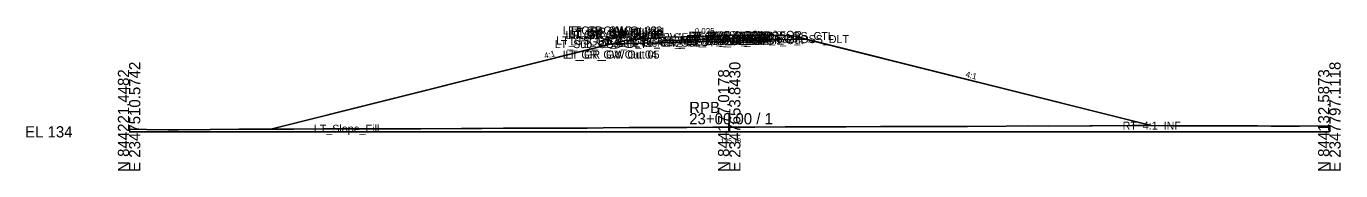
# Model space of a CAD drawing. Extents: x -76 to 2347760, y -10 to 844216.
# Drawn here: x -75.7 to 252.8, y 7990.3 to 8026.3 of the extents above; entities that cross this region are included whole.
import ezdxf

# ---------------------------------------------------------------- set-up
doc = ezdxf.new("R2010")
doc.units = 0
for name, color, linetype in [('Default', 7, 'Continuous'), ('Exist Cross Section Cell', 7, 'Continuous'), ('Exist XS Center Line Elevation Label', 7, 'Continuous'), ('Exist XS Ground Line', 7, 'Continuous'), ('Prop CMT Pvmt Course 1', 7, 'Continuous'), ('Prop CMT Pvmt Course 2', 7, 'Continuous'), ('Prop CMT Pvmt Course 3', 7, 'Continuous'), ('Prop CMT Pvmt Surface', 7, 'Continuous'), ('Prop CMT Pvmt Surface Shoulder', 7, 'Continuous'), ('Prop CMT Shld Paved Course 1', 7, 'Continuous'), ('Prop CMT Shld Paved Course 2', 7, 'Continuous'), ('Prop CMT Shld Paved Course 3', 7, 'Continuous'), ('Prop CMT Slope Grass', 7, 'Continuous'), ('Prop CMT Subgrade Earthwork', 7, 'Continuous'), ('Prop XS Earthwork Shape', 7, 'Continuous'), ('Prop XS Side Slope Text', 7, 'Continuous'), ('Scratch_Level_0', 7, 'Continuous')]:
    doc.layers.add(name, color=color, linetype=linetype)

msp = doc.modelspace()

# ---------------------------------------------------------------- linework, layer by layer
at = {"layer": 'Exist Cross Section Cell'}
for p, q in [((100, 8000), (100, 8004.67)), ((-50, 8000), (-16.56, 8000)), ((-50, 8000), (100, 8000)), ((-16.56, 8000), (-16.53, 8000)), ((100, 8000), (250, 8000))]:
    msp.add_line(p, q, dxfattribs=at)
at = {"layer": 'Exist XS Ground Line'}
for points in [[(-50, 8000.62), (-45.62, 8000.58), (-40.19, 8000.51), (-37.75, 8000.52), (-29.72, 8000.58), (-22.58, 8000.63), (-19.25, 8000.64), (-16.56, 8000.64)], [(-16.56, 8000.64), (-16.53, 8000.64)], [(-16.53, 8000.64), (-11.86, 8000.64), (-9.51, 8000.64), (-8.78, 8000.64), (-1.52, 8000.72), (1.69, 8000.75), (7.78, 8000.78), (12.16, 8000.78), (21.9, 8000.78), (22.63, 8000.78), (22.95, 8000.78), (33.1, 8000.79), (38.13, 8000.81), (43.57, 8000.88), (53.31, 8000.94), (54.04, 8000.94), (55.67, 8000.94), (64.51, 8000.95), (68.48, 8000.97), (74.98, 8001.05), (81.49, 8001.04)], [(81.49, 8001.04), (83.66, 8001.04), (85.45, 8001.05), (89.43, 8001.09), (95.92, 8001.17), (98.84, 8001.18), (100, 8001.18), (106.39, 8001.2), (114.01, 8001.25), (116.86, 8001.24), (123.19, 8001.23), (127.33, 8001.22), (129.19, 8001.24), (137.8, 8001.34), (144.37, 8001.32), (148.27, 8001.3), (156.95, 8001.35), (158.74, 8001.35), (159.54, 8001.36), (169.21, 8001.43), (174.72, 8001.45), (179.68, 8001.44), (190.15, 8001.53), (190.71, 8001.53), (200.62, 8001.56), (205.08, 8001.55), (211.09, 8001.53), (220.25, 8001.46), (221.56, 8001.46), (224.47, 8001.45), (232.03, 8001.46), (235.43, 8001.41), (242.5, 8001.41), (250, 8001.48)]]:
    msp.add_lwpolyline(points, dxfattribs=at)
at = {"layer": 'Prop CMT Pvmt Course 1'}
for p, q in [((100, 8023.99), (88, 8023.69)), ((88, 8023.69), (88, 8022.85)), ((88, 8022.85), (100, 8023.15)), ((100, 8023.99), (104, 8024.09)), ((100, 8023.15), (100, 8023.99)), ((100, 8023.99), (100, 8023.99)), ((100, 8023.99), (100, 8023.15)), ((100, 8023.15), (100, 8023.99)), ((100, 8023.15), (100, 8023.99)), ((100, 8023.99), (100, 8023.99)), ((100, 8023.99), (100, 8023.15)), ((100, 8023.15), (100, 8023.99)), ((104, 8023.25), (100, 8023.15)), ((100, 8023.15), (100, 8023.15)), ((100, 8023.15), (100, 8023.15)), ((104, 8024.09), (104, 8023.25))]:
    msp.add_line(p, q, dxfattribs=at)
at = {"layer": 'Prop CMT Pvmt Course 2'}
for p, q in [((88, 8022.85), (100, 8023.15)), ((100, 8023.15), (88, 8022.85)), ((88, 8022.85), (88, 8022.85)), ((104, 8023.25), (100, 8023.15)), ((100, 8023.15), (104, 8023.25)), ((100, 8023.15), (100, 8023.15)), ((100, 8023.15), (100, 8023.15)), ((104, 8023.25), (104, 8023.25))]:
    msp.add_line(p, q, dxfattribs=at)
at = {"layer": 'Prop CMT Pvmt Course 3'}
for p, q in [((100, 8023.15), (88, 8022.85)), ((88, 8022.85), (88, 8022.35)), ((100, 8023.15), (104, 8023.25)), ((100, 8022.65), (100, 8023.15)), ((100, 8022.65), (100, 8023.15)), ((104, 8023.25), (104, 8022.75)), ((88, 8022.35), (100, 8022.65)), ((104, 8022.75), (100, 8022.65))]:
    msp.add_line(p, q, dxfattribs=at)
at = {"layer": 'Prop CMT Pvmt Surface'}
for q in [(88, 8023.69), (104, 8024.09)]:
    msp.add_line((100, 8023.99), q, dxfattribs=at)
at = {"layer": 'Prop CMT Pvmt Surface Shoulder'}
for p, q in [((88, 8023.69), (84, 8023.59)), ((104, 8024.09), (108, 8024.19))]:
    msp.add_line(p, q, dxfattribs=at)
at = {"layer": 'Prop CMT Shld Paved Course 1'}
for p, q in [((88, 8023.69), (84, 8023.59)), ((84, 8023.59), (84, 8022.75)), ((84, 8022.75), (88, 8022.85)), ((88, 8022.85), (88, 8023.69)), ((104, 8024.09), (108, 8024.19)), ((104, 8023.25), (104, 8024.09)), ((108, 8023.35), (104, 8023.25)), ((108, 8024.19), (108, 8023.35))]:
    msp.add_line(p, q, dxfattribs=at)
at = {"layer": 'Prop CMT Shld Paved Course 2'}
for p, q in [((88, 8022.85), (84, 8022.75)), ((84, 8022.75), (88, 8022.85)), ((88, 8022.85), (88, 8022.85)), ((104, 8023.25), (108, 8023.35)), ((108, 8023.35), (104, 8023.25)), ((104, 8023.25), (104, 8023.25)), ((108, 8023.35), (108, 8023.35)), ((84, 8022.75), (84, 8022.75))]:
    msp.add_line(p, q, dxfattribs=at)
at = {"layer": 'Prop CMT Shld Paved Course 3'}
for p, q in [((88, 8022.85), (84, 8022.75)), ((88, 8022.35), (88, 8022.85)), ((104, 8023.25), (108, 8023.35)), ((104, 8022.75), (104, 8023.25)), ((108.99, 8022.88), (104, 8022.75)), ((108, 8023.35), (108.5, 8023.36)), ((108.5, 8023.36), (108.99, 8022.88)), ((83.5, 8022.74), (82.99, 8022.23)), ((82.99, 8022.23), (88, 8022.35)), ((84, 8022.75), (83.5, 8022.74))]:
    msp.add_line(p, q, dxfattribs=at)
at = {"layer": 'Prop CMT Slope Grass'}
for p, q in [((73.99, 8022.78), (-14.58, 8000.64)), ((84, 8023.59), (73.99, 8022.78)), ((108, 8024.19), (116, 8023.91)), ((116, 8023.91), (205.45, 8001.54))]:
    msp.add_line(p, q, dxfattribs=at)
at = {"layer": 'Prop CMT Subgrade Earthwork'}
for p, q in [((104, 8022.75), (108.99, 8022.88)), ((108.99, 8022.88), (119.1, 8023.13)), ((82.99, 8022.23), (70.51, 8021.91)), ((88, 8022.35), (82.99, 8022.23)), ((100, 8022.65), (88, 8022.35)), ((100, 8022.65), (104, 8022.75))]:
    msp.add_line(p, q, dxfattribs=at)
at = {"layer": 'Prop XS Earthwork Shape'}
msp.add_lwpolyline([(190.71, 8001.53), (200.62, 8001.56), (205.08, 8001.55), (205.45, 8001.54), (119.1, 8023.13), (108.99, 8022.88), (104, 8022.75), (100, 8022.65), (88, 8022.35), (82.99, 8022.23), (70.51, 8021.91), (-14.58, 8000.64), (-11.86, 8000.64), (-9.51, 8000.64), (-8.78, 8000.64), (-1.52, 8000.72), (1.69, 8000.75), (7.78, 8000.78), (12.16, 8000.78), (21.9, 8000.78), (22.63, 8000.78), (22.95, 8000.78), (33.1, 8000.79), (38.13, 8000.81), (43.57, 8000.88), (53.31, 8000.94), (54.04, 8000.94), (55.67, 8000.94), (64.51, 8000.95), (68.48, 8000.97), (74.98, 8001.05), (81.49, 8001.04), (83.66, 8001.04), (85.45, 8001.05), (89.43, 8001.09), (95.92, 8001.17), (98.84, 8001.18), (100, 8001.18), (106.39, 8001.2), (114.01, 8001.25), (116.86, 8001.24), (123.19, 8001.23), (127.33, 8001.22), (129.19, 8001.24), (137.8, 8001.34), (144.37, 8001.32), (148.27, 8001.3), (156.95, 8001.35), (158.74, 8001.35), (159.54, 8001.36), (169.21, 8001.43), (174.72, 8001.45), (179.68, 8001.44), (190.15, 8001.53)], close=True, dxfattribs=at)

# ---------------------------------------------------------------- texts
at = {"layer": 'Default'}
msp.add_text('-', height=0.0001, dxfattribs=at).set_placement((-50, 8000))
at = {"layer": 'Exist Cross Section Cell'}
for s, p in [('E 2347510.5742', (-47.2, 7990)), ('E 2347510.5742', (-47.2, 7990)), ('E 2347653.8430', (102.8, 7990)), ('E 2347797.1118', (252.8, 7990)), ('E 2347797.1118', (252.8, 7990)), ('N 844221.4482', (-50, 7990)), ('N 844221.4482', (-50, 7990)), ('N 844177.0178', (100, 7990)), ('N 844132.5873', (250, 7990)), ('N 844132.5873', (250, 7990))]:
    msp.add_text(s, height=2.8, rotation=90, dxfattribs=at).set_placement(p)
for s, p in [('RPB', (90, 8004.67)), ('23+00.00 / 1', (90, 8001.87)), ('EL 134', (-76, 7998.6)), ('EL 134', (-76, 7998.6))]:
    msp.add_text(s, height=2.8, dxfattribs=at).set_placement(p)
at = {"layer": 'Exist XS Center Line Elevation Label'}
msp.add_text('135.18', height=1.2, dxfattribs=at).set_placement((97.89, 7997.17))
at = {"layer": 'Prop XS Side Slope Text'}
for s, rotation, p in [('0.025', 1.4321, (91.38, 8024.32)), ('4:1', 14.0362, (53.91, 8018.19)), ('4:1', 345.9638, (158.96, 8013.69))]:
    msp.add_text(s, height=1.5, rotation=rotation, dxfattribs=at).set_placement(p)
at = {"layer": 'Scratch_Level_0'}
for s, p in [('LT_GR_GW Out 03', (58.43, 8024.28)), ('LT_GR_GW Out 02', (59.77, 8024.28)), ('LT_Sub_OSS_DLT', (56.39, 8020.88)), ('LT_GS_OS_GR_Face_GW', (56.75, 8021.78)), ('LT_GR_GW Out 06', (59.05, 8023.12)), ('LT_GR_GW Out 09', (59.77, 8023.7)), ('LT_GR_GW Out 07', (59.77, 8023.12)), ('LT_GR_GW Out 08', (60.04, 8023.41)), ('LT_GS_OS_CTL', (60.36, 8021.54)), ('LT_GR_GW Out 01', (60.6, 8023.99)), ('LT_Sub_Trench_Out', (67.19, 8021.23)), ('LT_PS3_Shelf_Out', (69.48, 8021.74)), ('LT_PS3_OEOP', (74.24, 8021.75)), ('LT_PS2_OEOP', (74.24, 8021.75)), ('LT_PS1_OEOP', (74.8, 8022.59)), ('LT_Sub_OEOT', (78.08, 8021.35)), ('LT_PV3_OEOT', (78.17, 8021.85)), ('LT_PV2_OEOT', (78.17, 8021.85)), ('LT_PV1_OEOT', (78.74, 8022.69)), ('RT_Sub_OEEOP', (89.17, 8021.65)), ('LT_Sub_OEEOP', (89.21, 8021.65)), ('RT_PV2_OEEOP', (89.26, 8022.15)), ('RT_PV3_OEEOP', (89.26, 8022.15)), ('LT_PV2_OEEOP', (89.31, 8022.15)), ('LT_PV3_OEEOP', (89.31, 8022.15)), ('RT_PV1_OEEOP', (89.83, 8022.99)), ('LT_PV1_OEEOP', (89.87, 8022.99)), ('RT_PV2_IEEOP', (89.91, 8022.15)), ('LT_PV2_IEEOP', (89.95, 8022.15)), ('RT_PV1_IEEOP', (90.47, 8022.99)), ('LT_PV1_IEEOP', (90.52, 8022.99)), ('RT_Sub_Trench_Out', (93.15, 8021.88)), ('PV2_PGL', (93.91, 8022.15)), ('RT_Sub_OEOT', (94.03, 8021.75)), ('RT_PV3_OEOT', (94.13, 8022.25)), ('RT_PV2_OEOT', (94.13, 8022.25)), ('RT_PS3_Shelf_Out', (94.44, 8022.36)), ('PV1_PGL', (94.47, 8022.99)), ('RT_PV1_OEOT', (94.69, 8023.09)), ('RT_PS3_OEOP', (98.19, 8022.35)), ('RT_PS2_OEOP', (98.19, 8022.35)), ('RT_PS1_OEOP', (98.76, 8023.19)), ('RT_GS_OS_CTL', (105.32, 8022.91)), ('RT_Sub_OSS_DLT', (106.46, 8022.13)), ('LT_GR_GW Out 04', (58.43, 8018.28)), ('LT_GR_GW Out 05', (59.1, 8018.28)), ('LT_Slope_Fill', (-3.82, 7999.77)), ('RT_4:1_INF', (198.33, 8000.54))]:
    msp.add_text(s, height=2, dxfattribs=at).set_placement(p)

doc.saveas('drawing.dxf')
